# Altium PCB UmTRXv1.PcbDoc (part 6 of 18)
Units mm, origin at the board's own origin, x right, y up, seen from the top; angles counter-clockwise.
Board outline 172 x 113 mm, 6 copper layers (Top Layer, GND, MidLayer1, Mid-Layer 2, InternalPlane2, Bottom Layer); 766 components, 613 nets, 3008 pads, 1360 vias.
Unrouted connection lines stored in the file: 2.
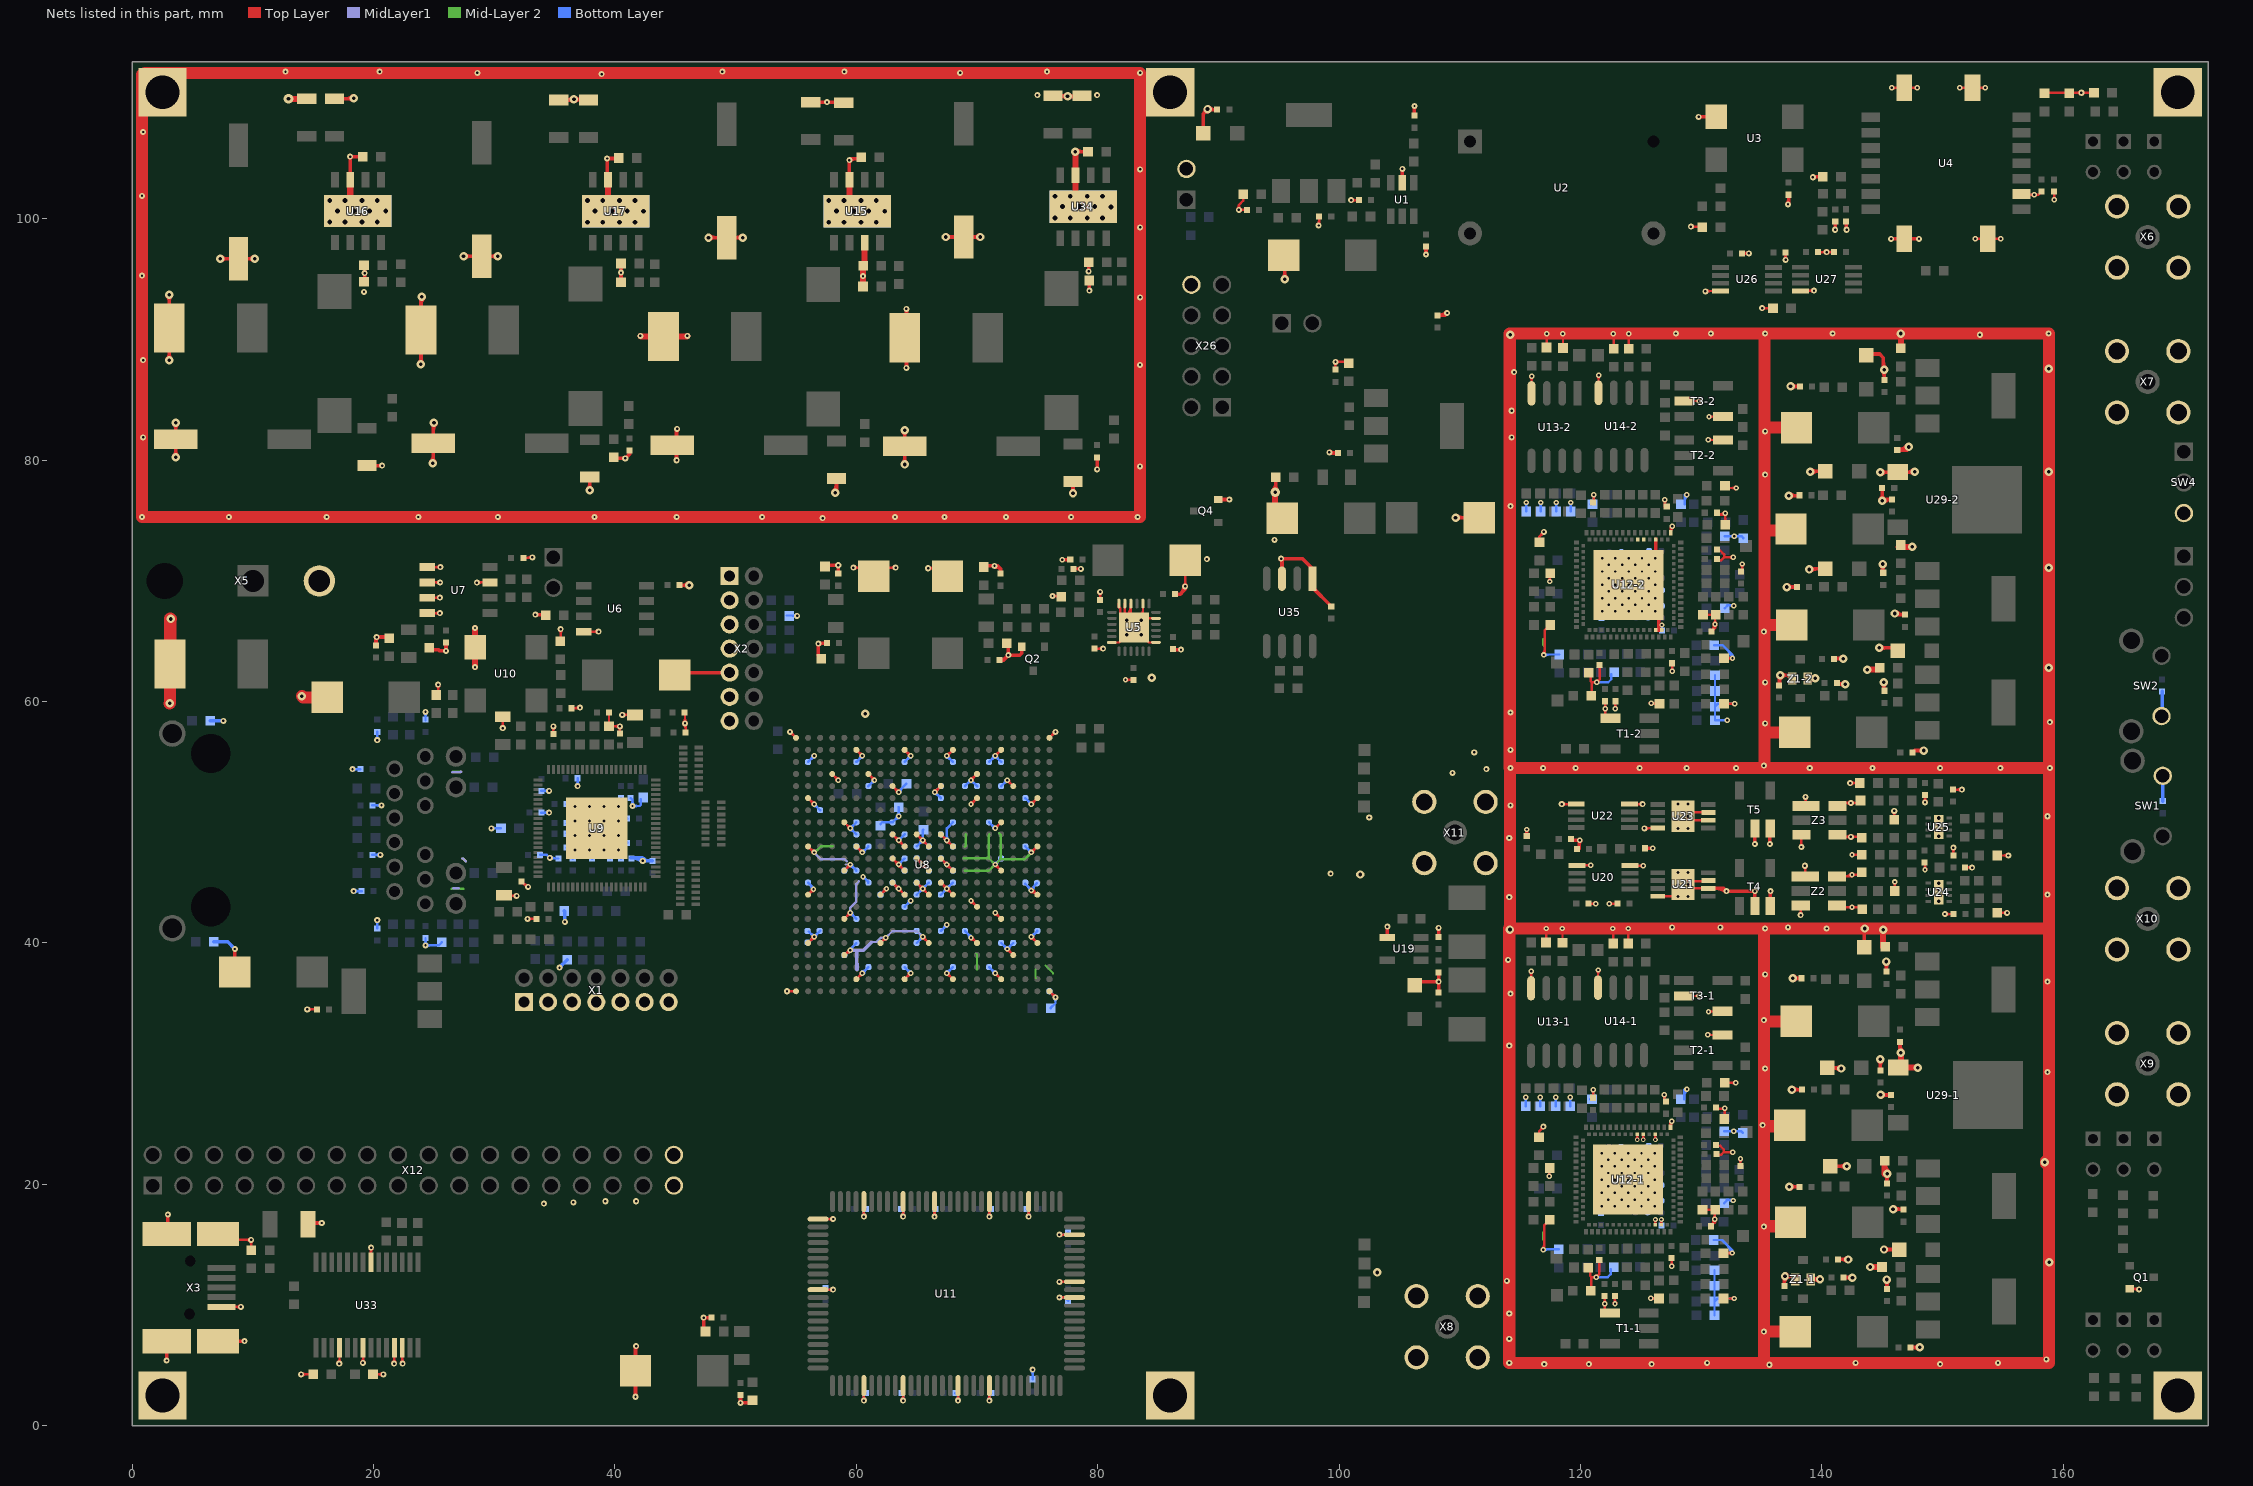
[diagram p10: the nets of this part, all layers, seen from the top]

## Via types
v1: diameter 0.45, hole 0.2, Top Layer to Bottom Layer, tented both sides, 554 vias
v2: diameter 0.5, hole 0.2, Top Layer to Bottom Layer, tented both sides, 468 vias
v3: diameter 0.7, hole 0.3, Top Layer to Bottom Layer, tented both sides, 206 vias
v4: diameter 0.4, hole 0.2, Top Layer to Bottom Layer, tented both sides, 82 vias
v5: diameter 0.8, hole 0.3, Top Layer to Bottom Layer, tented both sides, 16 vias
v6: diameter 0.6, hole 0.25, Top Layer to Bottom Layer, tented both sides, 16 vias
v7: diameter 0.5, hole 0.3, Top Layer to Bottom Layer, tented both sides, 8 vias
v8: diameter 0.7, hole 0.3, Top Layer to Bottom Layer, 4 vias
v9: diameter 0.6, hole 0.3, Top Layer to Bottom Layer, tented both sides, 4 vias
v10: diameter 0.5, hole 0.2, Top Layer to Bottom Layer, 2 vias

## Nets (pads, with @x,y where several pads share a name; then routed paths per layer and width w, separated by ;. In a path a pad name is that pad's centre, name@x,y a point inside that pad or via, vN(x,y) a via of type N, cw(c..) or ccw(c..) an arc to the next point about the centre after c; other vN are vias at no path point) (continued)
GND: C1.2 C2.2 C4.2 C5.1 C6.2 C7.2 C8.2 C10.2 C11.2 C12.2 C13.2 C14.1 C15.1 C17.2 C18.2 C19.2 C20.2 C21.2 C22.2 C24.2 C25.2 C26.2 C27.1 C28.2 C29.2 C30.2 C31.2 C32.1 C33.2 C34.2 C35.2 C36.2 C37.2 C38.2 C39.2 C40.2 C41.1 C42.2 C43.1 C44-1.2 C44-2.2 C45-1.1 C45-2.1 C46-1.2 C46-2.2 C47-1.2 C47-2.2 C48-1.2 C48-2.2 C49-1.2 C49-2.2 C50-1.2 C50-2.2 C51-1.2 C51-2.2 C52-1.2 C52-2.2 C53-1.2 C53-2.2 C54-1.2 C54-2.2 C55-1.2 C55-2.2 C56-1.2 C56-2.2 C57-1.2 C57-2.2 C58-1.2 C58-2.2 C59-1.1 C59-2.1 C60-1.1 C60-2.1 C61-1.1 C61-2.1 C62-1.1 C62-2.1 C63-1.1 C63-2.1 C64-1.2 C64-2.2 C65-1.2 C65-2.2 C66-1.2 C66-2.2 C67-1.2 C67-2.2 C68-1.2 C68-2.2 C69-1.2 C69-2.2 C70-1.2 C70-2.2 C71-1.2 C71-2.2 C72-1.2 C72-2.2 C73-1.2 C73-2.2 C74-1.2 C74-2.2 C75-1.2 C75-2.2 C76-1.2 C76-2.2 C77-1.2 C77-2.2 C78-1.2 C78-2.2 C79-1.2 C79-2.2 C80-1.2 C80-2.2 C81-1.2 C81-2.2 C82-1.2 C82-2.2 C84-1.1 C84-2.1 C85-1.1 C85-2.1 C86-1.2 C86-2.2 C87-1.2 C87-2.2 C88-1.2 C88-2.2 C89-1.2 C89-2.2 C90-1.2 C90-2.2 C91-1.2 C91-2.2 C92-1.2 C92-2.2 C93-1.2 C93-2.2 C94-1.1 C94-2.1 C95-1.2 C95-2.2 C97-1.1 C97-2.1 C98-1.2 C98-2.2 C100-1.2 C100-2.2 C101-1.2 C101-2.2 C108-1.2 C108-2.2 C109-1.2 C109-2.2 C113.2 C114.2 C115.2 C116.2 C117.2 C118.2 C119.2 C120.2 C121.2 C122.2 C123.2 C124.2 C125.2 C126.2 C127.2 C128.2 C129.2 C130.2 C131.2 C135.2 C136.2 C137.2 C138.2 C139.2 C140.2 C141.2 C142.2 C143.2 C144.2 C145.2 C146.2 C147.2 C148.2 C149.1 C150.2 C151.2 C152.2 C153.2 C154.2 C155.2 C156.2 C157.2 C158.2 C159.2 C160.2 C161.2 C162.2 C163.2 C164.2 C165.2 C166.2 C167.2 C168.2 C169.2 C171.2 C172.1 C174.1 C175.1 C176.1 C177.1 C178.1 C179.1 C180.1 C181.1 C182.1 C183.1 C184.1 C185.1 C186.1 C187.1 C188.1 C189.1 C190.1 C191.1 C192.1 C193.1 C194.1 C196.1 C197.1 C198.1 C199.1 C200.1 C201.1 C202.1 C203.1 C204.1 C205.1 C206.1 C207.1 C208.1 C209.1 C210.1 C211.1 C212.1 C213.1 C214.1 C215.1 C216.1 C217.1 C218.1 C219.1 C220.1 C221.1 C222.1 C223.1 C224.1 C225.1 C226.1 C227.1 C228.1 C229.2 C230.2 C231.2 C232.2 C233.2 C234.2 C235.2 C236.2 C237.2 C238.2 C239.2 C240.2 C241.2 C242.2 C243.2 C244.2 C245.2 C246.2 C247.2 C248.2 C249.2 C250.2 C251.2 C252.2 C254.2 C255.2 C256.2 C257.2 C258.2 C259.2 C260.2 C261.2 C262.2 C263.2 C264.2 C265.2 C266.2 C268.2 C269.2 C270.2 C271.2 C272.2 C273.2 C274.2 C275.1 C276.2 C277.2 C278.2 C279.2 C280.2 C281.2 C282.2 C283.2 C284.2 C285.2 C286.1 C287.1 C288.2 C289.2 C292.2 C293.2 C294.1 C295.1 C296.2 C297.2 C298.1 C299.1 C302.2 C303.2 C304.2 C305.2 C306.1 C308.1 C310.2 C311.2 C312.2 C313.1 C314.2 C315.1 C316.1 C317.2 C318.1 C319.1 D1.1 D2.1 D3.1 D4.1 D5.1 pad.0 Q1.2 Q2.2 Q4.2 R1.1 R5.1 R9.1 R12.1 R20.2 R23.1 R24.1 R25.2 R32.2 R39.1 R40.1 R56.1 R60.2 R61.2 R62.1 R66.1 R67.1 R78.2 R93.2 R96-1.1 R96-2.1 R97-1.1 R97-2.1 R98-1.1 R98-2.1 R106-1.1 R106-2.1 R107-1.1 R107-2.1 R108-1.1 R108-2.1 R110-1.1 R110-2.1 R111-1.1 R111-2.1 R112-1.1 R112-2.1 R113-1.1 R113-2.1 R120-1.1 R120-2.1 R121-1.2 R121-2.2 R122-1.2 R122-2.2 R123-1.1 R123-2.1 R124-1.2 R124-2.2 R128.1 R129.1 R130.1 R131.2 R132.2 R133.2 R135.2 R139.1 R140.1 R144.1 R146.1 R150.1 R153.1 R155-1.1 R155-2.1 R156-1.1 R156-2.1 R159-1.2 R159-2.2 R162.1 R168.1 R169.2 SW1.2 SW2.1 SW4.3 T1-1.6 T1-2.6 T2-1.4 T2-2.4 T3-1.2 T3-1.6 T3-2.2 T3-2.6 T4.1 T4.2 T5.1 T5.2 U1.2 U2.7 U3.2 U4.2 U4.8 U4.9 U4.17 U4.18 U5.0 U5.2 U5.4 U5.5 U5.6 U5.12 U5.19 U5.23 U6.4 U7.1 U7.2 U7.3 U7.4 U7.7 U8.A1 U8.A22 U8.AA5 U8.AA9 U8.AA13 U8.AA17 U8.AB1 U8.AB22 U8.B5 U8.B9 U8.B13 U8.B17 U8.D4 U8.D18 U8.E2 U8.E7 U8.E11 U8.E15 U8.E21 U8.G5 U8.G18 U8.H7 U8.J2 U8.J9 U8.J11 U8.J13 U8.J15 U8.J21 U8.K10 U8.K12 U8.K14 U8.L5 U8.L9 U8.L11 U8.L13 U8.L18 U8.M10 U8.M12 U8.M14 U8.N2 U8.N9 U8.N11 U8.N13 U8.N17 U8.N21 U8.P10 U8.P12 U8.P14 U8.R5 U8.R18 U8.U2 U8.U7 U8.U21 U8.V4 U8.V10 U8.V14 U8.W7 U8.W16 U8.W19 U9.0 U10.2 U11.5 U11.10 U11.17 U11.21 U11.26 U11.31 U11.40 U11.55 U11.60 U11.67 U11.71 U11.90 U11.92 U11.98 U12-1.0 U12-1.53 U12-1.55 U12-1.88 U12-1.93 U12-1.97 U12-1.99 U12-2.0 U12-2.53 U12-2.55 U12-2.88 U12-2.93 U12-2.97 U12-2.99 U13-1.4 U13-2.4 U14-1.4 U14-2.4 U15.0 U15.3 U15.7 U16.0 U16.7 U17.0 U17.7 U19.4 U20.4 U20.5 U21.0 U21.4 U21.6 U21.7 U22.4 U22.5 U23.0 U23.4 U23.6 U23.7 U24.0 U25.0 U26.4 U27.4 U29-1.1 U29-2.1 U33.7 U33.18 U33.21 U33.25 U33.26 U34.0 U34.7 U35.1 U35.3 X1.1 X1.3 X1.5 X1.7 X1.9 X1.11 X1.13 X2.1 X2.3 X2.5 X2.7 X2.9 X2.11 X2.13 X3.0 X3.4 X5.2 X6.2 X7.2 X8.2 X9.2 X10.2 X11.2 X12.35 X12.36 X26.10 X27.2 Z1-1.2 Z1-2.2 Z2.1 Z2.3 Z2.4 Z2.6 Z3.1 Z3.3 Z3.4 Z3.6 | length 1670.5
  Top Layer w0.15: v1@117.305,20.764 ccw(c117.049,21.02) 117.411,21.02 ccw(c117.773,21.02) v1@117.517,20.764 ; v1@117.344,70.056 ccw(c117.088,70.312) 117.45,70.312 ccw(c117.812,70.312) v1@117.556,70.056 ; v1(117.411,20.658) R159-1.2@117.411,21.308 ; v1(117.45,69.95) R159-2.2@117.45,70.6 ; T3-1.2@128.561,35.608 v1(129.811,35.608) ; T3-2.2@128.6,84.9 v1(129.85,84.9) ; v1@129.705,35.502 ccw(c129.449,35.246) 129.449,35.608 ccw(c129.449,35.97) v1@129.705,35.714 ; v1@129.744,84.794 ccw(c129.488,84.538) 129.488,84.9 ccw(c129.488,85.262) v1@129.744,85.006 ; v1(130.561,32.408) 130.591,32.378 T2-1.4@131.761,32.378 ; v1(130.6,81.7) 130.63,81.67 T2-2.4@131.8,81.67 ; v1(130.611,34.308) 130.641,34.338 T3-1.6@131.761,34.338 ; v1(130.65,83.6) 130.68,83.63 T3-2.6@131.8,83.63 ; v1@130.667,32.302 cw(c130.851,32.119) 130.851,32.378 ; v1@130.667,32.514 ccw(c130.996,32.843) T2-1.4@130.996,32.378 ; v1@130.706,81.594 cw(c130.89,81.41) 130.89,81.67 ; v1@130.706,81.806 ccw(c131.035,82.135) T2-2.4@131.035,81.67 ; v1@130.717,34.202 cw(c131.046,33.874) T3-1.6@131.046,34.338 ; v1@130.717,34.414 ccw(c130.901,34.598) 130.901,34.338 ; v1@130.756,83.494 cw(c131.085,83.165) T3-2.6@131.085,83.63 ; v1@130.756,83.706 ccw(c130.94,83.89) 130.94,83.63
  Top Layer w0.2: X3.0@7.1,15.9 7.6,15.4 v2(9.85,15.4) C316.1@9.85,14.55 ; X3.4@7.4,9.85 v2(9,9.85) ; v2@8.894,9.744 ccw(c8.638,9.488) 8.638,9.85 ccw(c8.638,10.212) v2@8.894,9.956 ; v2@9.744,15.506 cw(c9.488,15.762) 9.488,15.4 cw(c9.488,15.038) 9.744,15.294 cw(c9.488,15.038) 9.85,15.038 cw(c10.212,15.038) v2@9.956,15.294 ; v2(14,4.25) C319.1@15,4.25 ; v2@14.106,4.144 cw(c14.362,3.888) 14.362,4.25 cw(c14.362,4.612) v2@14.106,4.356 ; v2(14.5,34.5) C214.1@15.3,34.5 ; v2@14.606,34.394 cw(c14.862,34.138) 14.862,34.5 cw(c14.862,34.862) v2@14.606,34.606 ; v2@17.044,5.256 ccw(c16.727,5.573) 17.175,5.573 ; v2(17.15,5.15) 17.2,5.15 17.175,5.175 U33.18@17.175,6.45 ; 17.175,5.452 ccw(c17.452,5.452) v2@17.256,5.256 ; v2@18.994,5.306 ccw(c18.678,5.622) 19.125,5.622 ; v2(19.1,5.2) 19.125,5.225 U33.21@19.125,6.45 ; 19.125,5.502 ccw(c19.402,5.502) v2@19.206,5.306 ; v2@19.694,14.644 cw(c19.498,14.448) 19.775,14.448 ; U33.7@19.775,13.55 19.775,14.725 v2(19.8,14.75) ; U33.7@19.775,14.328 cw(c20.222,14.328) v2@19.906,14.644 ; C318.1@19.95,4.25 v2(20.8,4.25) ; v2@20.694,4.144 ccw(c20.438,3.888) 20.438,4.25 ccw(c20.438,4.612) v2@20.694,4.356 ; v2@21.594,5.256 ccw(c21.278,5.572) 21.725,5.572 ; v2(21.7,5.15) 21.75,5.2 21.725,5.225 U33.25@21.725,6.45 ; 21.725,5.452 ccw(c22.002,5.452) v2@21.806,5.256 ; v2@22.294,5.256 ccw(c22.098,5.452) 22.375,5.452 ; 22.375,5.572 ccw(c22.822,5.572) v2@22.506,5.256 ; U33.26@22.375,6.45 22.375,5.175 v2(22.4,5.15) ; U7.4@24.437,67.337 25.481,67.337 v2(25.495,67.324) ; U7.3@24.437,68.607 25.473,68.607 v2(25.481,68.615) ; U7.2@24.437,69.877 25.499,69.877 v2(25.507,69.869) ; U7.1@24.437,71.147 25.532,71.147 v2(25.533,71.148) ; 25.099,68.607 ccw(c25.099,68.997) v2@25.375,68.721 ; 25.1,67.337 cw(c25.1,66.929) v2@25.388,67.218 ; 25.125,69.877 cw(c25.125,69.487) v2@25.401,69.763 ; 25.139,68.607 cw(c25.139,68.273) v2@25.375,68.509 ; 25.165,67.337 ccw(c25.165,67.653) v2@25.388,67.43 ; 25.165,69.877 ccw(c25.165,70.211) v2@25.401,69.975 ; 25.168,71.147 ccw(c25.168,71.513) v2@25.427,71.254 ; 25.173,71.147 cw(c25.173,70.788) v2@25.427,71.042 ; v2@25.244,61.294 cw(c24.988,61.038) 25.35,61.038 cw(c25.712,61.038) v2@25.456,61.294 ; R78.2@25.35,60.55 v2(25.35,61.4) ; v2(28.552,69.856) 28.572,69.877 U7.7@29.647,69.877 ; v2@28.658,69.75 cw(c28.964,69.445) 28.964,69.877 ; v2@28.658,69.963 ccw(c28.864,70.169) 28.864,69.877 ; v2@30.594,57.906 ccw(c30.338,58.162) 30.7,58.162 ccw(c31.062,58.162) v2@30.806,57.906 ; v2(30.7,57.8) C283.2@30.7,58.75 ; C285.2@30.8,43.95 30.85,43.9 v2(31.85,43.9) ; v2@31.744,43.794 ccw(c31.488,43.538) 31.488,43.9 ccw(c31.488,44.262) v2@31.744,44.006 ; C287.1@32.25,45.1 32.7,44.65 v2(32.8,44.65) ; C287.1@32.373,44.977 ccw(c32.8,45.404) v2@32.8,44.8 ; C27.1@32.4,71.9 v2@33.156,71.9 ; 32.667,71.9 ccw(c32.667,72.433) v2@33.044,72.056 ; v2(32.75,42) C228.1@33.4,42 ; v2@32.856,41.894 cw(c33.112,41.638) 33.112,42 cw(c33.112,42.362) v2@32.856,42.106 ; v2@34.794,57.844 cw(c34.538,57.588) 34.9,57.588 cw(c35.262,57.588) v2@35.006,57.844 ; C240.2@34.9,57.3 v2(34.9,57.95) ; v2@35.394,65.894 cw(c35.138,65.638) 35.5,65.638 cw(c35.862,65.638) v2@35.606,65.894 ; R62.1@35.5,65.05 v2(35.5,66) ; C37.2@36.4,59.45 37.05,59.45 v2(37.1,59.5) ; C37.2@36.617,59.45 ccw(c36.617,59.983) v2@36.994,59.606 ; U6.4@37.45,65.8 v2(38.65,65.8) v2@38.658,65.8 ; v2@38.544,65.694 ccw(c38.288,65.438) 38.288,65.8 ccw(c38.288,66.162) v2@38.544,65.906 ; C40.2@39.5,59.1 R56.1@39.5,57.95 v2(40.4,57.95) C286.1@40.4,57.35 ; v2@40.294,58.056 cw(c40.038,58.312) 40.038,57.95 cw(c40.038,57.588) 40.294,57.844 cw(c40.038,57.588) 40.4,57.588 cw(c40.762,57.588) v2@40.506,57.844 ; v2(40.6,58.9) 40.65,58.9 C284.2@41.65,58.9 ; v2@40.706,58.794 cw(c40.962,58.538) 40.962,58.9 cw(c40.962,59.262) v2@40.706,59.006 ; v2@45.694,58.094 cw(c45.317,57.717) 45.85,57.717 ; v2@45.694,58.306 ccw(c45.438,58.562) 45.8,58.562 ccw(c46.162,58.562) v2@45.906,58.306 ; C39.2@45.75,59.1 45.8,59.05 v2(45.8,58.2) 45.85,58.15 C42.2@45.85,57.45 ; v2(54.25,36) U8.A22@55,36 ; v2@54.356,35.894 cw(c54.612,35.638) 54.612,36 cw(c54.612,36.362) v2@54.356,36.106 ; v2@54.5,57.35 cw(c54.5,56.988) 54.756,57.244 cw(c55.012,57.5) v2@54.65,57.5 ; v2(54.5,57.5) U8.AB22@55,57 ; U8.E21@56,40 v1(56.5,40.5) ; U8.J21@56,44 v1@56.5,44.5 ; U8.N21@56,48 v1(56.5,47.5) ; U8.U21@56,52 v1(56.5,51.5) ; v1@56.3,44.45 cw(c55.938,44.45) 56.194,44.194 cw(c56.45,43.938) v1@56.45,44.3 ; v1@56.35,40.5 cw(c55.988,40.5) 56.244,40.244 cw(c56.5,39.988) v1@56.5,40.35 ; v1@56.35,47.5 ccw(c55.988,47.5) 56.244,47.756 ccw(c56.5,48.012) v1@56.5,47.65 ; v1@56.35,51.5 ccw(c55.988,51.5) 56.244,51.756 ccw(c56.5,52.012) v1@56.5,51.65 ; U11.40@56.825,11.275 v2(58.075,11.275) ; U11.31@56.825,17.125 v2(58.075,17.125) ; v2@57.969,11.169 ccw(c57.713,10.913) 57.713,11.275 ccw(c57.713,11.637) v2@57.969,11.381 ; v2@57.969,17.019 ccw(c57.713,16.763) 57.713,17.125 ccw(c57.713,17.487) v2@57.969,17.231 ; U8.W19@58,54 v1(58.5,53.5) ; v1@58.35,53.5 ccw(c57.988,53.5) 58.244,53.756 ccw(c58.5,54.012) v1@58.5,53.65 ; U8.D18@59,39 v1@59.5,39.5 ; U8.G18@59,42 v1(59.5,42.5) ; U8.L18@59,46 v1(59.5,46.5) ; U8.R18@59,50 v1(59.5,49.5) ; U8.D18@59.073,39.073 cw(c59.5,38.646) v1@59.5,39.25 ; v1@59.35,42.5 cw(c58.988,42.5) 59.244,42.244 cw(c59.5,41.988) v1@59.5,42.35 ; v1@59.35,46.5 cw(c58.988,46.5) 59.244,46.244 cw(c59.5,45.988) v1@59.5,46.35 ; v1@59.35,49.5 ccw(c58.988,49.5) 59.244,49.756 ccw(c59.5,50.012) v1@59.5,49.65 ; v2@59.8,71.1 v2(63.25,71.1) v2@63.3,71.1 ; v2@59.856,70.994 cw(c60.112,70.738) 60.112,71.1 cw(c60.112,71.462) v2@59.856,71.206 ; U8.B17@60,37 v1(60.5,37.5) ; U8.N17@60,48 v1(60.5,47.5) ; U8.AA17@60,56 v1(60.5,55.5) ; v1@60.35,37.5 cw(c59.988,37.5) 60.244,37.244 cw(c60.5,36.988) v1@60.5,37.35 ; v1@60.35,47.5 ccw(c59.988,47.5) 60.244,47.756 ccw(c60.5,48.012) v1@60.5,47.65 ; v1@60.35,55.5 ccw(c59.988,55.5) 60.244,55.756 ccw(c60.5,56.012) v1@60.5,55.65 ; v2@60.519,2.181 ccw(c60.263,2.437) 60.625,2.437 ccw(c60.987,2.437) v2@60.731,2.181 ; v2@60.519,17.431 ccw(c60.263,17.687) 60.625,17.687 ccw(c60.987,17.687) v2@60.731,17.431 ; v2(60.625,2.075) U11.55@60.625,3.325 ; v2(60.625,17.325) U11.26@60.625,18.575 ; U8.W16@61,54 v1(61.5,53.5) ; v1@61.35,53.5 ccw(c60.988,53.5) 61.244,53.756 ccw(c61.5,54.012) v1@61.5,53.65 ; C166.2@61.45,70.4 C166.2@61.5,70.45 ; U8.E15@62,40 v1(62.45,40.45) ; U8.J15@62,44 v1(62.5,44.5) ; v1@62.3,40.45 cw(c61.938,40.45) 62.194,40.194 cw(c62.45,39.938) v1@62.45,40.3 ; v1@62.35,44.5 cw(c61.988,44.5) 62.244,44.244 cw(c62.5,43.988) v1@62.5,44.35 ; U8.K14@63,45 v1(63.5,44.5) U8.J13@64,44 ; U8.M14@63,47 v1(63.5,46.5) U8.L13@64,46 ; U8.P14@63,49 v1(63.5,48.5) U8.N13@64,48 ; U8.V14@63,53 v1(63.5,52.5) ; v2@63.144,70.994 ccw(c62.888,70.738) 62.888,71.1 ccw(c62.888,71.462) v2@63.144,71.206 ; v1@63.35,44.5 ccw(c62.988,44.5) 63.244,44.756 ccw(c63.5,45.012) v1@63.5,44.65 ; v1@63.35,46.5 ccw(c62.988,46.5) 63.244,46.756 ccw(c63.5,47.012) v1@63.5,46.65 ; v1@63.35,48.5 ccw(c62.988,48.5) 63.244,48.756 ccw(c63.5,49.012) v1@63.5,48.65 ; v1@63.35,52.5 ccw(c62.988,52.5) 63.244,52.756 ccw(c63.5,53.012) v1@63.5,52.65 ; v1@63.5,44.35 cw(c63.5,43.988) 63.756,44.244 cw(c64.012,44.5) v1@63.65,44.5 ; v1@63.5,46.35 cw(c63.5,45.988) 63.756,46.244 cw(c64.012,46.5) v1@63.65,46.5 ; v1@63.5,48.35 cw(c63.5,47.988) 63.756,48.244 cw(c64.012,48.5) v1@63.65,48.5 ; v2@63.769,2.181 ccw(c63.513,2.437) 63.875,2.437 ccw(c64.237,2.437) v2@63.981,2.181 ; v2@63.769,17.431 ccw(c63.513,17.687) 63.875,17.687 ccw(c64.237,17.687) v2@63.981,17.431 ; v2(63.875,2.075) U11.60@63.875,3.325 ; v2(63.875,17.325) U11.21@63.875,18.575 ; U8.B13@64,37 v1(64.5,37.5) ; U8.AA13@64,56 v1(64.5,55.5) ; v1@64.35,37.5 cw(c63.988,37.5) 64.244,37.244 cw(c64.5,36.988) v1@64.5,37.35 ; v1@64.35,55.5 ccw(c63.988,55.5) 64.244,55.756 ccw(c64.5,56.012) v1@64.5,55.65 ; U8.K12@65,45 v1(65.5,44.5) U8.J11@66,44 ; U8.M12@65,47 v1(65.5,46.5) U8.L11@66,46 ; U8.P12@65,49 v1(65.5,48.5) U8.N11@66,48 ; v1@65.35,44.5 ccw(c64.988,44.5) 65.244,44.756 ccw(c65.5,45.012) v1@65.5,44.65 ; v1@65.35,46.5 ccw(c64.988,46.5) 65.244,46.756 ccw(c65.5,47.012) v1@65.5,46.65 ; v1@65.35,48.5 ccw(c64.988,48.5) 65.244,48.756 ccw(c65.5,49.012) v1@65.5,48.65 ; v1@65.5,40.35 cw(c65.5,39.988) 65.756,40.244 cw(c66.012,40.5) v1@65.65,40.5 ; v1(65.5,40.5) U8.E11@66,40 ; v1@65.5,44.35 cw(c65.5,43.988) 65.756,44.244 cw(c66.012,44.5) v1@65.65,44.5 ; v1@65.5,46.35 cw(c65.5,45.988) 65.756,46.244 cw(c66.012,46.5) v1@65.65,46.5 ; v1@65.5,48.35 cw(c65.5,47.988) 65.756,48.244 cw(c66.012,48.5) v1@65.65,48.5 ; v2(65.95,71.05) 66.9,71.05 C165.2@67.55,70.4 ; v2@66.056,70.944 cw(c66.312,70.688) 66.312,71.05 cw(c66.312,71.412) v2@66.056,71.156 ; v2@66.369,17.431 ccw(c66.113,17.687) 66.475,17.687 ccw(c66.837,17.687) v2@66.581,17.431 ; v2(66.475,17.325) U11.17@66.475,18.575 ; v1(66.5,52.5) U8.V10@67,53 ; v1@66.5,52.65 ccw(c66.5,53.012) 66.756,52.756 ccw(c67.012,52.5) v1@66.65,52.5 ; U8.K10@67,45 v1(67.5,44.5) U8.J9@68,44 ; U8.M10@67,47 v1(67.5,46.5) U8.L9@68,46 ; U8.P10@67,49 v1(67.5,48.5) U8.N9@68,48 ; v1@67.35,44.5 ccw(c66.988,44.5) 67.244,44.756 ccw(c67.5,45.012) v1@67.5,44.65 ; v1@67.35,46.5 ccw(c66.988,46.5) 67.244,46.756 ccw(c67.5,47.012) v1@67.5,46.65 ; v1@67.35,48.5 ccw(c66.988,48.5) 67.244,48.756 ccw(c67.5,49.012) v1@67.5,48.65 ; v1@67.5,37.35 cw(c67.5,36.988) 67.756,37.244 cw(c68.012,37.5) v1@67.65,37.5 ; v1(67.5,37.5) U8.B9@68,37 ; v1@67.5,44.35 cw(c67.5,43.988) 67.756,44.244 cw(c68.012,44.5) v1@67.65,44.5 ; v1@67.5,46.35 cw(c67.5,45.988) 67.756,46.244 cw(c68.012,46.5) v1@67.65,46.5 ; v1@67.5,48.35 cw(c67.5,47.988) 67.756,48.244 cw(c68.012,48.5) v1@67.65,48.5 ; v1(67.5,55.5) U8.AA9@68,56 ; v1@67.5,55.65 ccw(c67.5,56.012) 67.756,55.756 ccw(c68.012,55.5) v1@67.65,55.5 ; v2@68.319,2.181 ccw(c68.063,2.437) 68.425,2.437 ccw(c68.787,2.437) v2@68.531,2.181 ; v2(68.425,2.075) U11.67@68.425,3.325 ; v1@69.5,40.3 cw(c69.5,39.817) U8.E7@69.842,40.158 ; v1@69.5,40.5 U8.E7@70,40 ; v1@69.5,43.35 cw(c69.5,42.988) 69.756,43.244 cw(c70.012,43.5) v1@69.65,43.5 ; v1(69.5,43.5) U8.H7@70,43 ; v1(69.5,51.5) U8.U7@70,52 ; v1@69.5,51.65 ccw(c69.5,52.012) 69.756,51.756 ccw(c70.012,51.5) v1@69.65,51.5 ; v1(69.5,53.5) U8.W7@70,54 ; v1@69.5,53.65 ccw(c69.5,54.012) 69.756,53.756 ccw(c70.012,53.5) v1@69.65,53.5 ; v1@69.65,40.45 ccw(c69.891,40.45) 69.72,40.28 ; v2@70.919,2.181 ccw(c70.663,2.437) 71.025,2.437 ccw(c71.387,2.437) v2@71.131,2.181 ; v2@70.919,17.431 ccw(c70.663,17.687) 71.025,17.687 ccw(c71.387,17.687) v2@71.131,17.431 ; v2(71.025,2.075) U11.71@71.025,3.325 ; v2(71.025,17.325) U11.10@71.025,18.575 ; v1@71.5,37.35 cw(c71.5,36.988) 71.756,37.244 cw(c72.012,37.5) v1@71.65,37.5 ; v1(71.5,37.5) U8.B5@72,37 ; v1@71.5,42.35 cw(c71.5,41.988) 71.756,42.244 cw(c72.012,42.5) v1@71.65,42.5 ; v1(71.5,42.5) U8.G5@72,42 ; v1@71.5,46.35 cw(c71.5,45.988) 71.756,46.244 cw(c72.012,46.5) v1@71.65,46.5 ; v1(71.5,46.5) U8.L5@72,46 ; v1(71.5,49.5) U8.R5@72,50 ; v1@71.5,49.65 ccw(c71.5,50.012) 71.756,49.756 ccw(c72.012,49.5) v1@71.65,49.5 ; v1(71.5,55.5) U8.AA5@72,56 ; v1@71.5,55.65 ccw(c71.5,56.012) 71.756,55.756 ccw(c72.012,55.5) v1@71.65,55.5 ; v1@72.5,39.35 cw(c72.5,38.988) 72.756,39.244 cw(c73.012,39.5) v1@72.65,39.5 ; v1(72.5,39.5) U8.D4@73,39 ; v1@72.5,53.35 cw(c72.5,52.988) 72.756,53.244 cw(c73.012,53.5) v1@72.65,53.5 ; v1(72.5,53.5) U8.V4@73,53 ; v2@74.169,17.431 ccw(c73.913,17.687) 74.275,17.687 ccw(c74.637,17.687) v2@74.381,17.431 ; v2(74.275,17.325) U11.5@74.275,18.575 ; v1@74.5,40.35 cw(c74.5,39.988) 74.756,40.244 cw(c75.012,40.5) v1@74.65,40.5 ; v1(74.5,40.5) U8.E2@75,40 ; v1@74.5,44.5 U8.J2@75,44 ccw(c74.517,43.517) v1@74.503,44.2 ; v1(74.5,47.5) U8.N2@75,48 ; v1@74.5,47.65 ccw(c74.5,48.012) 74.756,47.756 ccw(c75.012,47.5) v1@74.65,47.5 ; v1(74.5,51.5) U8.U2@75,52 ; v1@74.5,51.65 ccw(c74.5,52.012) 74.756,51.756 ccw(c75.012,51.5) v1@74.65,51.5 ; U8.A1@76,36 v2(76.5,35.5) ; U8.AB1@76,57 v2(76.5,57.5) ; v2(76.25,68.75) 76.924,68.75 C19.2@76.987,68.687 ; v2@76.35,35.5 ccw(c75.988,35.5) 76.244,35.756 ccw(c76.5,36.012) v2@76.5,35.65 ; v2@76.35,57.5 cw(c75.988,57.5) 76.244,57.244 cw(c76.5,56.988) v2@76.5,57.35 ; v2@76.356,68.644 cw(c76.612,68.388) 76.612,68.75 cw(c76.612,69.112) v2@76.356,68.856 ; v2(76.825,10.625) U11.90@78.075,10.625 ; v2(76.825,11.925) U11.92@78.075,11.925 ; v2(76.825,15.825) U11.98@78.075,15.825 ; v2@76.931,10.519 cw(c77.187,10.263) 77.187,10.625 cw(c77.187,10.987) v2@76.931,10.731 ; v2@76.931,11.819 cw(c77.187,11.563) 77.187,11.925 cw(c77.187,12.287) v2@76.931,12.031 ; v2@76.931,15.719 cw(c77.187,15.463) 77.187,15.825 cw(c77.187,16.187) v2@76.931,15.931 ; C24.2@78,71 v2(78.6,71) ; v2@78.494,70.894 ccw(c78.238,70.638) 78.238,71 ccw(c78.238,71.362) v2@78.494,71.106 ; C14.1@79.9,64.388 v2(80.45,64.388) ; v2@80.094,68.994 cw(c79.838,68.738) 80.2,68.738 ; C15.1@80.2,68.438 v2(80.2,69.1) ; 80.2,68.738 cw(c80.562,68.738) v2@80.306,68.994 ; v2@80.344,64.282 ccw(c80.088,64.025) 80.088,64.388 ccw(c80.088,64.75) v2@80.344,64.494 ; U5.12@81.175,64.9 81.75,64.9 U5.0@83,66.15 ; U5.6@81.75,68.125 81.75,67.85 81.85,67.75 81.85,67.3 U5.0@82.25,66.9 ; U5.0@82.2,65.55 cw(c81.717,65.55) 82.059,65.209 cw(c82.4,64.867) U5.0@82.4,65.35 ; U5.0@82.2,66.75 ccw(c81.717,66.75) 82.059,67.091 ccw(c82.4,67.433) U5.0@82.4,66.95 ; U5.0@82.25,67.112 ccw(c82.762,67.112) v9(82.4,66.75) ; 82.25,67.595 ccw(c83.245,67.595) U5.0@82.541,66.891 ; U5.5@82.25,68.125 U5.0@82.25,66.9 ; U5.0@82.259,66.891 ccw(c81.072,68.078) U5.4@82.75,68.078 ; v1(82.3,61.8) C22.2@82.9,61.8 ; v1@82.388,61.712 cw(c82.602,61.498) 82.602,61.8 cw(c82.602,62.102) v1@82.388,61.888 ; U5.0@82.4,65.75 ccw(c82.4,66.233) 82.741,65.891 ccw(c83.083,65.55) U5.0@82.6,65.55 ; U5.0@82.4,66.55 cw(c82.4,66.067) 82.741,66.409 cw(c83.083,66.75) U5.0@82.6,66.75 ; U5.0@82.541,66.609 ccw(c82.038,67.112) U5.0@82.75,67.112 ; 82.75,67.595 cw(c81.555,67.595) v9(82.4,66.75) ; U5.4@82.75,68.125 U5.0@82.75,66.4 ; U5.0@83.4,65.55 ccw(c82.917,65.55) 83.259,65.891 ccw(c83.6,66.233) U5.0@83.6,65.75 ; U5.0@83.4,66.75 cw(c82.917,66.75) 83.259,66.409 cw(c83.6,66.067) U5.0@83.6,66.55 ; U5.0@83.459,66.891 ccw(c82.755,67.595) 83.75,67.595 ; U5.0@83.6,65.35 cw(c83.6,64.867) 83.941,65.209 cw(c84.283,65.55) U5.0@83.8,65.55 ; U5.0@83.741,66.609 cw(c84.445,65.905) U5.23@84.445,66.9 ; U5.0@83.75,67.112 cw(c83.238,67.112) v9(83.6,66.75) ; U5.2@83.75,68.125 U5.0@83.75,66.9 ; U5.0@83.962,66.9 ccw(c83.962,66.388) v9(83.6,66.75) ; U5.19@84.825,64.9 84.25,64.9 v9(83.6,65.55) U5.0@83,66.15 ; U5.23@84.825,66.9 U5.0@83.75,66.9 ; v2@87.144,69.656 ccw(c86.888,69.912) 87.25,69.912 ccw(c87.612,69.912) v2@87.356,69.656 ; v2(87.25,69.55) C17.2@87.25,71.3 ; v2@91.594,100.856 ccw(c91.338,101.112) 91.7,101.112 ccw(c92.062,101.112) 91.806,100.856 ccw(c92.062,101.112) 92.062,100.75 ccw(c92.062,100.388) v2@91.806,100.644 ; R5.1@92.05,102.05 92.05,101.5 91.7,101.15 v2(91.7,100.75) C278.2@92.35,100.75 ; v2@98.194,99.556 ccw(c97.817,99.933) 98.35,99.933 ; v2(98.3,99.45) 98.3,99.4 98.35,99.45 C7.2@98.35,100.2 ; v2@99.594,88.044 cw(c99.338,87.788) 99.7,87.788 cw(c100.062,87.788) 99.806,88.044 cw(c100.062,87.788) 100.062,88.15 cw(c100.062,88.512) v2@99.806,88.256 ; C135.2@99.7,87.5 v2(99.7,88.15) 100.7,88.15 R135.2@100.8,88.05 ; v2(101,101.55) C4.2@101.65,101.55 ; v2@101.106,101.444 cw(c101.362,101.188) 101.362,101.55 cw(c101.362,101.912) v2@101.106,101.656 ; v1@115.823,37.57 cw(c115.621,37.369) 115.906,37.369 ; v1@115.862,86.862 cw(c115.66,86.66) 115.945,86.66 ; U13-1.4@115.906,36.249 115.906,37.653 v1(115.911,37.658) ; 115.906,37.344 cw(c116.225,37.344) v1@115.999,37.57 ; U13-2.4@115.945,85.541 115.945,86.945 v1(115.95,86.95) ; 115.945,86.636 cw(c116.264,86.636) v1@116.038,86.862 ; C76-1.2@116.562,23.905 116.562,24.367 116.937,24.742 116.928,24.751 v2(116.928,24.775) ; C76-2.2@116.601,73.197 116.601,73.659 116.976,74.034 116.967,74.043 v2(116.967,74.067) ; 116.643,24.448 ccw(c116.315,24.775) v2@116.778,24.775 ; 116.682,73.74 ccw(c116.354,74.067) v2@116.817,74.067 ; 116.743,24.549 cw(c116.928,24.364) v2@116.928,24.625 ; 116.782,73.841 cw(c116.967,73.656) v2@116.967,73.917 ; v1@116.833,14.662 ccw(c116.451,15.044) 116.991,15.044 ; v1@116.872,63.954 ccw(c116.49,64.335) 117.03,64.335 ; v1@116.991,14.539 116.991,16.588 R155-1.1@117.461,17.058 ; v1@117.03,63.831 117.03,65.88 R155-2.1@117.5,66.35 ; v1@117.08,41.112 cw(c116.867,40.898) 117.168,40.898 cw(c117.47,40.898) v1@117.257,41.112 ; v1@117.119,90.403 cw(c116.905,90.19) 117.207,90.19 cw(c117.509,90.19) v1@117.296,90.403 ; C100-1.2@117.146,40.044 117.168,40.066 v1(117.168,41.2) ; C100-2.2@117.185,89.336 117.207,89.358 v1(117.207,90.492) ; v1@118.401,41.112 cw(c118.135,40.846) 118.511,40.846 ; v1@118.44,90.403 cw(c118.174,90.138) 118.55,90.138 ; v2(118.45,51.5) 118.456,51.506 U22.5@119.651,51.506 ; v1(118.489,41.2) 118.511,41.178 C101-1.2@118.511,40.008 ; 118.511,40.951 cw(c118.739,40.951) v1@118.578,41.112 ; v1(118.528,90.492) 118.55,90.47 C101-2.2@118.55,89.3 ; 118.55,90.242 cw(c118.778,90.242) v1@118.617,90.403 ; v2@118.556,51.394 cw(c118.826,51.124) 118.826,51.506 ; v2@118.556,51.606 ccw(c118.798,51.848) 118.798,51.506 ; U20.5@119.701,46.431 120.876,46.431 120.901,46.456 v1(120.851,46.456) ; 120.489,46.431 ccw(c120.489,46.818) v1@120.763,46.544 ; 120.61,46.431 cw(c120.61,46.214) v1@120.763,46.367 ; C294.1@120.651,43.256 v1(121.251,43.256) ; C77-1.2@120.657,13.088 120.811,12.934 120.811,12.408 120.911,12.308 ; C77-2.2@120.696,62.38 120.85,62.226 120.85,61.7 120.95,61.6 ; C68-1.2@120.857,11.188 120.911,11.242 120.911,12.308 ; C68-2.2@120.896,60.48 120.95,60.534 120.95,61.6 ; v1@120.969,27.75 cw(c120.755,27.536) 121.057,27.536 cw(c121.359,27.536) v1@121.145,27.75 ; v1@121.008,77.041 cw(c120.794,76.828) 121.096,76.828 cw(c121.398,76.828) v1@121.184,77.041 ; C86-1.2@121.057,27.188 v1(121.057,27.838) ; C86-2.2@121.096,76.48 v1(121.096,77.13) ; v1@121.163,43.167 ccw(c120.95,42.954) 120.95,43.256 ccw(c120.95,43.558) v1@121.163,43.344 ; v1@121.223,12.22 ccw(c121.009,12.006) 121.009,12.308 ccw(c121.009,12.61) v1@121.223,12.397 ; v1@121.262,61.512 ccw(c121.048,61.298) 121.048,61.6 ccw(c121.048,61.902) v1@121.262,61.688 ; v1@121.311,12.433 ccw(c121.311,12.735) 121.524,12.522 ccw(c121.738,12.308) v1@121.436,12.308 ; v1@121.35,61.725 ccw(c121.35,62.027) 121.563,61.813 ccw(c121.777,61.6) v1@121.475,61.6 ; v1@121.373,37.67 cw(c121.171,37.469) 121.456,37.469 ; v1@121.412,86.962 cw(c121.21,86.76) 121.495,86.76 ; U14-1.4@121.456,36.299 121.456,37.753 v1(121.461,37.758) ; 121.456,37.444 cw(c121.775,37.444) v1@121.549,37.67 ; U14-2.4@121.495,85.591 121.495,87.045 v1(121.5,87.05) ; 121.495,86.736 cw(c121.814,86.736) v1@121.588,86.962 ; C63-1.1@121.557,13.738 121.557,12.554 v1(121.311,12.308) 120.911,12.308 ; C63-2.1@121.596,63.03 121.596,61.846 v1(121.35,61.6) 120.95,61.6 ; v1@121.923,10.02 cw(c121.709,9.806) 122.011,9.806 cw(c122.313,9.806) v1@122.099,10.02 ; v1@121.923,10.197 ccw(c121.719,10.4) 122.007,10.4 ; T1-1.6@121.933,9.3 122.011,9.378 v1(122.011,10.108) 122.007,10.112 C85-1.1@122.007,10.738 ; v1@121.962,59.312 cw(c121.748,59.098) 122.05,59.098 cw(c122.352,59.098) v1@122.138,59.312 ; v1@121.962,59.488 ccw(c121.758,59.692) 122.046,59.692 ; T1-2.6@121.972,58.592 122.05,58.67 v1(122.05,59.4) 122.046,59.404 C85-2.1@122.046,60.03 ; 122.007,10.42 ccw(c122.323,10.42) v1@122.099,10.197 ; 122.046,59.712 ccw(c122.362,59.712) v1@122.138,59.488 ; v1(122.401,43.256) C292.2@123.051,43.256 ; v1@122.49,43.167 cw(c122.703,42.954) 122.703,43.256 cw(c122.703,43.558) v1@122.49,43.344 ; v1@122.581,41.112 cw(c122.266,40.797) 122.711,40.797 ; v1@122.62,90.403 cw(c122.305,90.089) 122.75,90.089 ; v1(122.669,41.2) 122.711,41.158 C108-1.2@122.711,39.958 ; v1(122.708,90.492) 122.75,90.45 C108-2.2@122.75,89.25 ; v1@122.773,10.197 ccw(c122.569,10.4) 122.857,10.4 ; v1@122.812,59.488 ccw(c122.608,59.692) 122.896,59.692 ; 122.857,10.42 ccw(c123.173,10.42) v1@122.949,10.197 ; C94-1.1@122.857,10.738 122.857,10.162 122.911,10.108 v1(122.861,10.108) ; 122.896,59.712 ccw(c123.212,59.712) v1@122.988,59.488 ; C94-2.1@122.896,60.03 122.896,59.454 122.95,59.4 v1(122.9,59.4) ; v1@123.858,41.112 cw(c123.61,40.863) 123.961,40.863 ; v1@123.897,90.403 cw(c123.649,90.155) 124,90.155 ; v1(123.947,41.2) 123.961,41.186 C109-1.2@123.961,39.958 ; 123.961,40.933 cw(c124.214,40.933) v1@124.035,41.112 ; v1(123.986,90.492) 124,90.477 C109-2.2@124,89.25 ; 124,90.225 cw(c124.252,90.225) v1@124.074,90.403 ; U22.4@124.051,51.506 125.144,51.506 v2(125.15,51.5) ; U20.4@124.125,46.4 v1(125.2,46.4) ; v4@124.636,23.759 ccw(c124.466,23.93) 124.707,23.93 ccw(c124.948,23.93) v4@124.778,23.759 ; v4@124.707,23.713 U12-1.99@124.707,24.138 ; 124.774,51.506 cw(c124.774,51.124) v2@125.044,51.394 ; 124.802,51.506 ccw(c124.802,51.848) v2@125.044,51.606 ; v1@125.112,46.312 ccw(c124.898,46.098) 124.898,46.4 ccw(c124.898,46.702) v1@125.112,46.488 ; v4@125.136,23.759 ccw(c124.966,23.93) 125.207,23.93 ccw(c125.448,23.93) v4@125.278,23.759 ; v4@125.207,23.713 U12-1.97@125.207,24.138 ; v2@125.4,49.5 125.425,49.525 U23.4@126.45,49.525 ; v2@125.406,49.394 cw(c125.722,49.078) 125.722,49.525 ; v2@125.406,49.606 ccw(c125.602,49.802) 125.602,49.525 ; v1(125.811,10.558) 125.711,10.558 125.731,10.538 C95-1.2@126.507,10.538 ; v1(125.85,59.85) 125.75,59.85 125.77,59.83 C95-2.2@126.546,59.83 ; v1@125.899,10.47 cw(c126.064,10.305) 126.064,10.538 ; v1@125.899,10.647 ccw(c126.162,10.909) C95-1.2@126.162,10.538 ; v1@125.938,59.762 cw(c126.103,59.597) 126.103,59.83 ; v1@125.938,59.938 ccw(c126.2,60.2) C95-2.2@126.2,59.83 ; v4@126.136,17.017 cw(c125.966,16.847) 126.207,16.847 cw(c126.448,16.847) v4@126.278,17.017 ; v4@126.136,23.759 ccw(c125.966,23.93) 126.207,23.93 ccw(c126.448,23.93) v4@126.278,23.759 ; U12-1.53@126.207,16.638 v4@126.207,17.063 ; v4@126.207,23.713 U12-1.93@126.207,24.138 ; U21.4@126.4,43.875 U21.0@127.975,43.875 ; v4@126.636,17.017 cw(c126.466,16.847) 126.707,16.847 cw(c126.948,16.847) v4@126.778,17.017 ; U12-1.55@126.707,16.638 v4@126.707,17.063 ; v1@126.869,27.35 cw(c126.655,27.136) 126.957,27.136 cw(c127.259,27.136) v1@127.045,27.35 ; v1@126.908,76.641 cw(c126.694,76.428) 126.996,76.428 cw(c127.298,76.428) v1@127.084,76.641 ; C90-1.2@126.957,26.838 v1(126.957,27.438) ; C90-2.2@126.996,76.13 v1(126.996,76.73) ; U12-1.88@127.457,24.704 cw(c128.079,24.704) v1@127.644,25.149 ; U12-1.88@127.457,24.713 127.457,25.138 127.607,25.288 v1(127.557,25.238) ; v1@127.473,13.297 ccw(c127.269,13.5) 127.557,13.5 ; U12-2.88@127.496,73.995 cw(c128.118,73.995) v1@127.683,74.441 ; U12-2.88@127.496,74.005 127.496,74.43 127.646,74.58 v1(127.596,74.53) ; v1@127.512,62.588 ccw(c127.308,62.792) 127.596,62.792 ; 127.557,13.52 ccw(c127.873,13.52) v1@127.649,13.297 ; C87-1.2@127.557,13.888 127.557,13.212 v1(127.561,13.208) ; 127.596,62.812 ccw(c127.912,62.812) v1@127.688,62.588 ; C87-2.2@127.596,63.18 127.596,62.504 v1(127.6,62.5) ; U21.0@127.876,44.481 127.901,44.456 U21.0@128.401,45.456 ; U21.0@128.726,45.781 U21.0@128.401,45.456 ; U21.0@128.815,44.525 U21.6@130.6,44.525 ; v2(129.15,99.35) 130.05,99.35 R12.1@130.1,99.3 ; v2@129.256,99.244 cw(c129.512,98.988) 129.512,99.35 cw(c129.512,99.712) v2@129.256,99.456 ; R156-1.1@130.111,17.908 C45-1.1@131.161,17.908 131.111,17.858 v1(131.111,17.108) 131.111,16.822 ; R156-2.1@130.15,67.2 C45-2.1@131.2,67.2 131.15,67.15 v1(131.15,66.4) 131.15,66.114 ; v2(130.35,94) 130.371,94.021 U26.4@131.608,94.021 ; v2@130.456,93.894 cw(c130.762,93.588) 130.762,94.021 ; v2@130.456,94.106 ccw(c130.663,94.313) 130.663,94.021 ; U21.7@130.501,45.131 128.726,45.131 U21.0@128.401,45.456 ; U23.6@130.65,50.175 U23.6@130.6,50.175 128.875,50.175 128.55,50.5 128.875,50.825 U23.7@130.61,50.825 U23.7@130.66,50.825 ; v1@130.988,17.085 cw(c130.375,16.969) C59-1.1@130.816,16.527 131.111,16.822 ; v1@131.023,17.197 ccw(c130.809,17.41) 131.111,17.41 ccw(c131.413,17.41) v1@131.199,17.197 ; v1@131.026,17.017 cw(c130.846,16.822) 131.111,16.822 ; v1@131.027,66.377 cw(c130.414,66.26) C59-2.1@130.855,65.819 131.15,66.114 ; v1@131.062,66.488 ccw(c130.848,66.702) 131.15,66.702 ccw(c131.452,66.702) v1@131.238,66.488 ; v1@131.065,66.308 cw(c130.885,66.114) 131.15,66.114 ; 131.084,16.795 ccw(c130.824,17.054) v1@131.185,17.122 ; 131.123,66.086 ccw(c130.863,66.346) v1@131.224,66.414 ; v1@131.196,17.017 ccw(c131.376,16.822) 131.111,16.822 ; v1@131.235,66.308 ccw(c131.415,66.114) 131.15,66.114 ; C91-1.2@131.257,22.438 131.641,22.438 131.861,22.658 ; C61-1.1@131.257,23.188 131.269,23.2 131.569,23.2 131.861,22.908 131.861,22.658 ; C93-1.2@131.266,26.275 v1@131.85,26.275 ; C91-2.2@131.296,71.73 131.68,71.73 131.9,71.95 ; C61-2.1@131.296,72.48 131.316,72.5 131.6,72.5 131.9,72.2 131.9,71.95 ; C93-2.2@131.296,75.48 131.88,75.48 v1(132,75.6) 132,74.7 132.2,74.5 132.15,74.5 C97-2.1@131.95,74.7 ; C93-2.2@131.408,75.48 ccw(c131.408,76.192) v1@131.912,75.688 ; R106-1.1@131.857,10.538 v1(132.757,10.538) ; C84-1.1@131.857,14.288 132.541,14.288 v1(132.561,14.308) ; v1@131.873,26.22 cw(c131.659,26.006) 131.961,26.006 cw(c132.263,26.006) v1@132.049,26.22 ; R106-2.1@131.896,59.83 v1(132.796,59.83) ; C84-2.1@131.896,63.58 132.58,63.58 v1(132.6,63.6) ; C97-1.1@131.911,25.408 132.111,25.208 132.161,25.208 131.961,25.408 v1(131.961,26.308) ; v1@131.912,75.512 cw(c131.698,75.298) 132,75.298 cw(c132.302,75.298) v1@132.088,75.512 ; R108-1.1@131.961,28.408 v1(132.861,28.408) ; R108-2.1@132,77.7 v1(132.9,77.7) ; C84-1.1@132.211,14.288 ccw(c132.211,14.659) v1@132.473,14.397 ; C84-2.1@132.25,63.58 ccw(c132.25,63.95) v1@132.512,63.688 ; 132.308,14.288 cw(c132.308,14.055) v1@132.473,14.22 ; 132.347,63.58 cw(c132.347,63.347) v1@132.512,63.512 ; v1@132.523,22.57 ccw(c132.309,22.356) 132.309,22.658 ccw(c132.309,22.96) v1@132.523,22.747 ; v1@132.562,71.862 ccw(c132.348,71.648) 132.348,71.95 ccw(c132.348,72.252) v1@132.562,72.038 ; v1(132.611,22.658) 131.861,22.658 ; v1(132.65,71.95) 131.9,71.95 ; v1@132.669,10.45 ccw(c132.455,10.236) 132.455,10.538 ccw(c132.455,10.84) v1@132.669,10.626 ; v1@132.708,59.741 ccw(c132.494,59.528) 132.494,59.83 ccw(c132.494,60.132) v1@132.708,59.918 ; v1@132.773,28.32 ccw(c132.559,28.106) 132.559,28.408 ccw(c132.559,28.71) v1@132.773,28.497 ; v1@132.812,77.612 ccw(c132.598,77.398) 132.598,77.7 ccw(c132.598,78.002) v1@132.812,77.788 ; v1@133.173,22.02 cw(c132.959,21.806) 133.261,21.806 cw(c133.563,21.806) v1@133.349,22.02 ; C60-1.1@133.261,21.508 v1(133.261,22.108) ; v1@133.312,71.312 cw(c133.098,71.098) 133.4,71.098 cw(c133.702,71.098) v1@133.488,71.312 ; C60-2.1@133.4,70.8 v1(133.4,71.4) ; C312.2@133.403,97.14 133.89,97.14 133.9,97.15 v2(133.95,97.15) ; C312.2@133.564,97.14 ccw(c133.564,97.536) v2@133.844,97.256 ; C312.2@133.612,97.14 cw(c133.612,96.812) v2@133.844,97.044 ; v2(135.05,92.6) R153.1@135.85,92.6 ; v2@135.156,92.494 cw(c135.412,92.238) 135.412,92.6 cw(c135.412,92.962) v2@135.156,92.706 ; v2@136.894,96.706 ccw(c136.638,96.962) 137,96.962 ccw(c137.362,96.962) v2@137.106,96.706 ; v2(137,96.6) C313.1@137,97.2 ; v2@138.144,42.406 ccw(c137.885,42.665) 138.251,42.665 ; v2@138.194,48.056 ccw(c137.935,48.315) 138.301,48.315 ; U27.4@138.221,94.036 139.336,94.036 v2(139.35,94.05) ; v2(138.25,42.3) v2(138.25,42.3) Z2.3@138.251,43.106 ; 138.251,42.659 ccw(c138.609,42.659) v2@138.356,42.406 ; v2(138.3,47.95) 138.301,47.951 Z3.3@138.301,48.956 ; 138.301,48.309 ccw(c138.659,48.309) v2@138.406,48.056 ; v2@138.494,46.294 cw(c138.174,45.974) 138.626,45.974 ; v2@138.544,51.994 cw(c138.224,51.674) Z3.1@138.676,51.674 ; v2(138.6,46.4) 138.626,46.374 Z2.1@138.626,45.506 ; 138.626,46.101 cw(c138.899,46.101) v2@138.706,46.294 ; v2(138.65,52.1) 138.676,52.074 Z3.1@138.676,51.356 ; 138.676,51.801 cw(c138.949,51.801) v2@138.756,51.994 ; 138.954,94.036 ccw(c138.954,94.446) v2@139.244,94.156 ; 139.021,94.036 cw(c139.021,93.721) v2@139.244,93.944 ; C314.2@139.7,97.25 v2(140.4,97.25) C315.1@141,97.25 ; v2@140.294,97.144 ccw(c140.038,96.888) 140.038,97.25 ccw(c140.038,97.612) v2@140.294,97.356 ; v2@140.506,97.144 cw(c140.762,96.888) 140.762,97.25 cw(c140.762,97.612) v2@140.506,97.356 ; Z2.4@141.251,43.106 141.401,42.956 v1(142.501,42.956) 143.201,42.956 R139.1@143.351,42.806 ; Z2.6@141.251,45.506 142.351,45.506 v1(142.501,45.656) 143.101,45.656 C302.2@143.301,45.856 ; Z3.4@141.301,48.956 141.457,48.8 v2(142.4,48.8) 143.207,48.8 R140.1@143.301,48.706 ; Z3.6@141.301,51.356 141.546,51.6 v2(142.4,51.6) 142.996,51.6 C303.2@143.201,51.806 ; Z2.6@141.837,45.506 ccw(c141.837,46.32) v1@142.413,45.744 ; v2@142.294,48.694 ccw(c142.038,48.438) 142.038,48.8 ccw(c142.038,49.162) v2@142.294,48.906 ; v2@142.294,51.494 ccw(c142.038,51.238) 142.038,51.6 ccw(c142.038,51.962) v2@142.294,51.706 ; 142.32,45.506 ccw(c142.32,45.837) v1@142.554,45.603 ; v2(142.35,53.25) 142.356,53.256 C305.2@143.151,53.256 ; v1@142.413,42.867 ccw(c142.2,42.654) 142.2,42.956 ccw(c142.2,43.258) v1@142.413,43.044 ; v2@142.456,53.144 cw(c142.726,52.874) 142.726,53.256 ; v2@142.456,53.356 ccw(c142.698,53.598) 142.698,53.256 ; v1(142.501,47.306) C304.2@143.301,47.306 ; v2@142.506,48.694 cw(c142.762,48.438) 142.762,48.8 cw(c142.762,49.162) v2@142.506,48.906 ; v2@142.506,51.494 cw(c142.762,51.238) 142.762,51.6 cw(c142.762,51.962) v2@142.506,51.706 ; v1@142.59,42.867 cw(c142.803,42.654) 142.803,42.956 cw(c142.803,43.258) v1@142.59,43.044 ; v1@142.59,45.567 cw(c142.803,45.354) 142.803,45.656 cw(c142.803,45.958) v1@142.59,45.744 ; v1@142.59,47.217 cw(c142.803,47.004) 142.803,47.306 cw(c142.803,47.608) v1@142.59,47.394 ; v1(145.78,110.85) U4.9@146.84,110.85 v1(147.9,110.85) ; v1@145.868,110.762 cw(c146.082,110.548) 146.082,110.85 cw(c146.082,111.152) v1@145.868,110.938 ; v2@145.894,50.844 cw(c145.635,50.585) R146.1@146.001,50.585 ; v1@145.963,44.967 cw(c145.75,44.754) 146.051,44.754 cw(c146.353,44.754) v1@146.14,44.967 ; v2(146,50.95) 146,50.9 146.001,50.899 R146.1@146.001,50.206 ; R146.1@146.001,50.591 cw(c146.359,50.591) v2@146.106,50.844 ; R144.1@146.051,44.306 v1(146.051,45.056) ; v1@147.812,110.762 ccw(c147.598,110.548) 147.598,110.85 ccw(c147.598,111.152) v1@147.812,110.938 ; v2@148.444,51.756 ccw(c148.185,52.015) C299.1@148.551,52.015 ; v1@148.463,46.144 ccw(c148.25,46.358) 148.551,46.358 ccw(c148.853,46.358) v1@148.64,46.144 ; v2(148.55,51.65) v2(148.55,51.65) C299.1@148.551,52.256 ; v1(148.551,46.056) C298.1@148.551,46.656 ; C299.1@148.551,52.009 ccw(c148.909,52.009) v2@148.656,51.756 ; v7(149.7,43.45) v7(149.7,43.95) U24.0@149.7,44.2 v7(149.7,44.45) v7(149.7,44.95) ; v7(149.701,48.856) v7(149.701,49.356) U25.0@149.701,49.606 v7(149.701,49.856) v7(149.701,50.356) ; v2(150.2,42.4) C306.1@150.9,42.4 ; v2@150.306,42.294 cw(c150.562,42.038) 150.562,42.4 cw(c150.562,42.762) v2@150.306,42.506 ; v2@150.794,47.794 cw(c150.535,47.535) 150.901,47.535 ; C297.2@150.851,52.706 151.594,52.706 v2(151.6,52.7) ; v2(150.9,47.9) 150.9,47.8 150.901,47.799 C296.2@150.901,47.256 ; 150.901,47.541 cw(c151.259,47.541) v2@151.006,47.794 ; 151.224,52.706 cw(c151.224,52.324) v2@151.494,52.594 ; 151.252,52.706 ccw(c151.252,53.048) v2@151.494,52.806 ; v1(151.43,110.85) U4.8@152.49,110.85 v1(153.55,110.85) ; v1@151.518,110.762 cw(c151.732,110.548) 151.732,110.85 cw(c151.732,111.152) v1@151.518,110.938 ; C308.1@151.851,46.256 152.444,46.256 v2(152.45,46.25) ; C308.1@152.074,46.256 cw(c152.074,45.874) v2@152.344,46.144 ; 152.102,46.256 ccw(c152.102,46.598) v2@152.344,46.356 ; v1(152.7,98.35) U4.18@153.76,98.35 v1(154.82,98.35) ; v1@152.788,98.262 cw(c153.002,98.048) 153.002,98.35 cw(c153.002,98.652) v1@152.788,98.438 ; v1@153.462,110.762 ccw(c153.248,110.548) 153.248,110.85 ccw(c153.248,111.152) v1@153.462,110.938 ; C310.2@154.55,42.5 v2(155.35,42.5) ; C311.2@154.55,47.25 v2(155.45,47.25) ; v1@154.732,98.262 ccw(c154.518,98.048) 154.518,98.35 ccw(c154.518,98.652) v1@154.732,98.438 ; v2@155.244,42.394 ccw(c154.988,42.138) 154.988,42.5 ccw(c154.988,42.862) v2@155.244,42.606 ; v2@155.344,47.144 ccw(c155.088,46.888) 155.088,47.25 ccw(c155.088,47.612) v2@155.344,47.356 ; U4.2@156.55,102.01 157.59,102.01 v1(157.6,102) 157.95,102 C2.2@158.2,102.25 ; U4.2@157.274,102.01 cw(c157.274,101.674) v1@157.512,101.912 ; 157.322,102.01 ccw(c157.322,102.278) v1@157.512,102.088 ; v1@157.688,101.912 cw(c157.902,101.698) 157.902,102 cw(c157.902,102.302) v1@157.688,102.088 ; R66.1@158.45,110.4 158.5,110.45 v2(161.5,110.45) R1.1@162.55,110.45 ; v1@159.162,101.688 ccw(c158.948,101.902) 159.25,101.902 ccw(c159.552,101.902) v1@159.338,101.688 ; v1(159.25,101.6) C1.2@159.25,102.25 C1.2@159.25,102.3 ; v2@161.394,110.344 ccw(c161.138,110.088) 161.138,110.45 ccw(c161.138,110.812) v2@161.394,110.556 ; v2@161.606,110.344 cw(c161.862,110.088) 161.862,110.45 cw(c161.862,110.812) v2@161.606,110.556 ; Q1.2@165.5,11.35 166.25,11.35 166.3,11.4 v2(166.3,11.3) ; Q1.2@165.817,11.35 cw(c165.817,10.817) v2@166.194,11.194 ; U5.0@82.25,66.9 v9(82.4,66.75) ; v9(82.4,66.75) U5.0@82.75,66.4 ; U5.0@82.75,66.4 U5.0@83,66.15 ; U5.0@83,66.15 v9(83.6,66.75) ; v9(83.6,66.75) U5.0@83.75,66.9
